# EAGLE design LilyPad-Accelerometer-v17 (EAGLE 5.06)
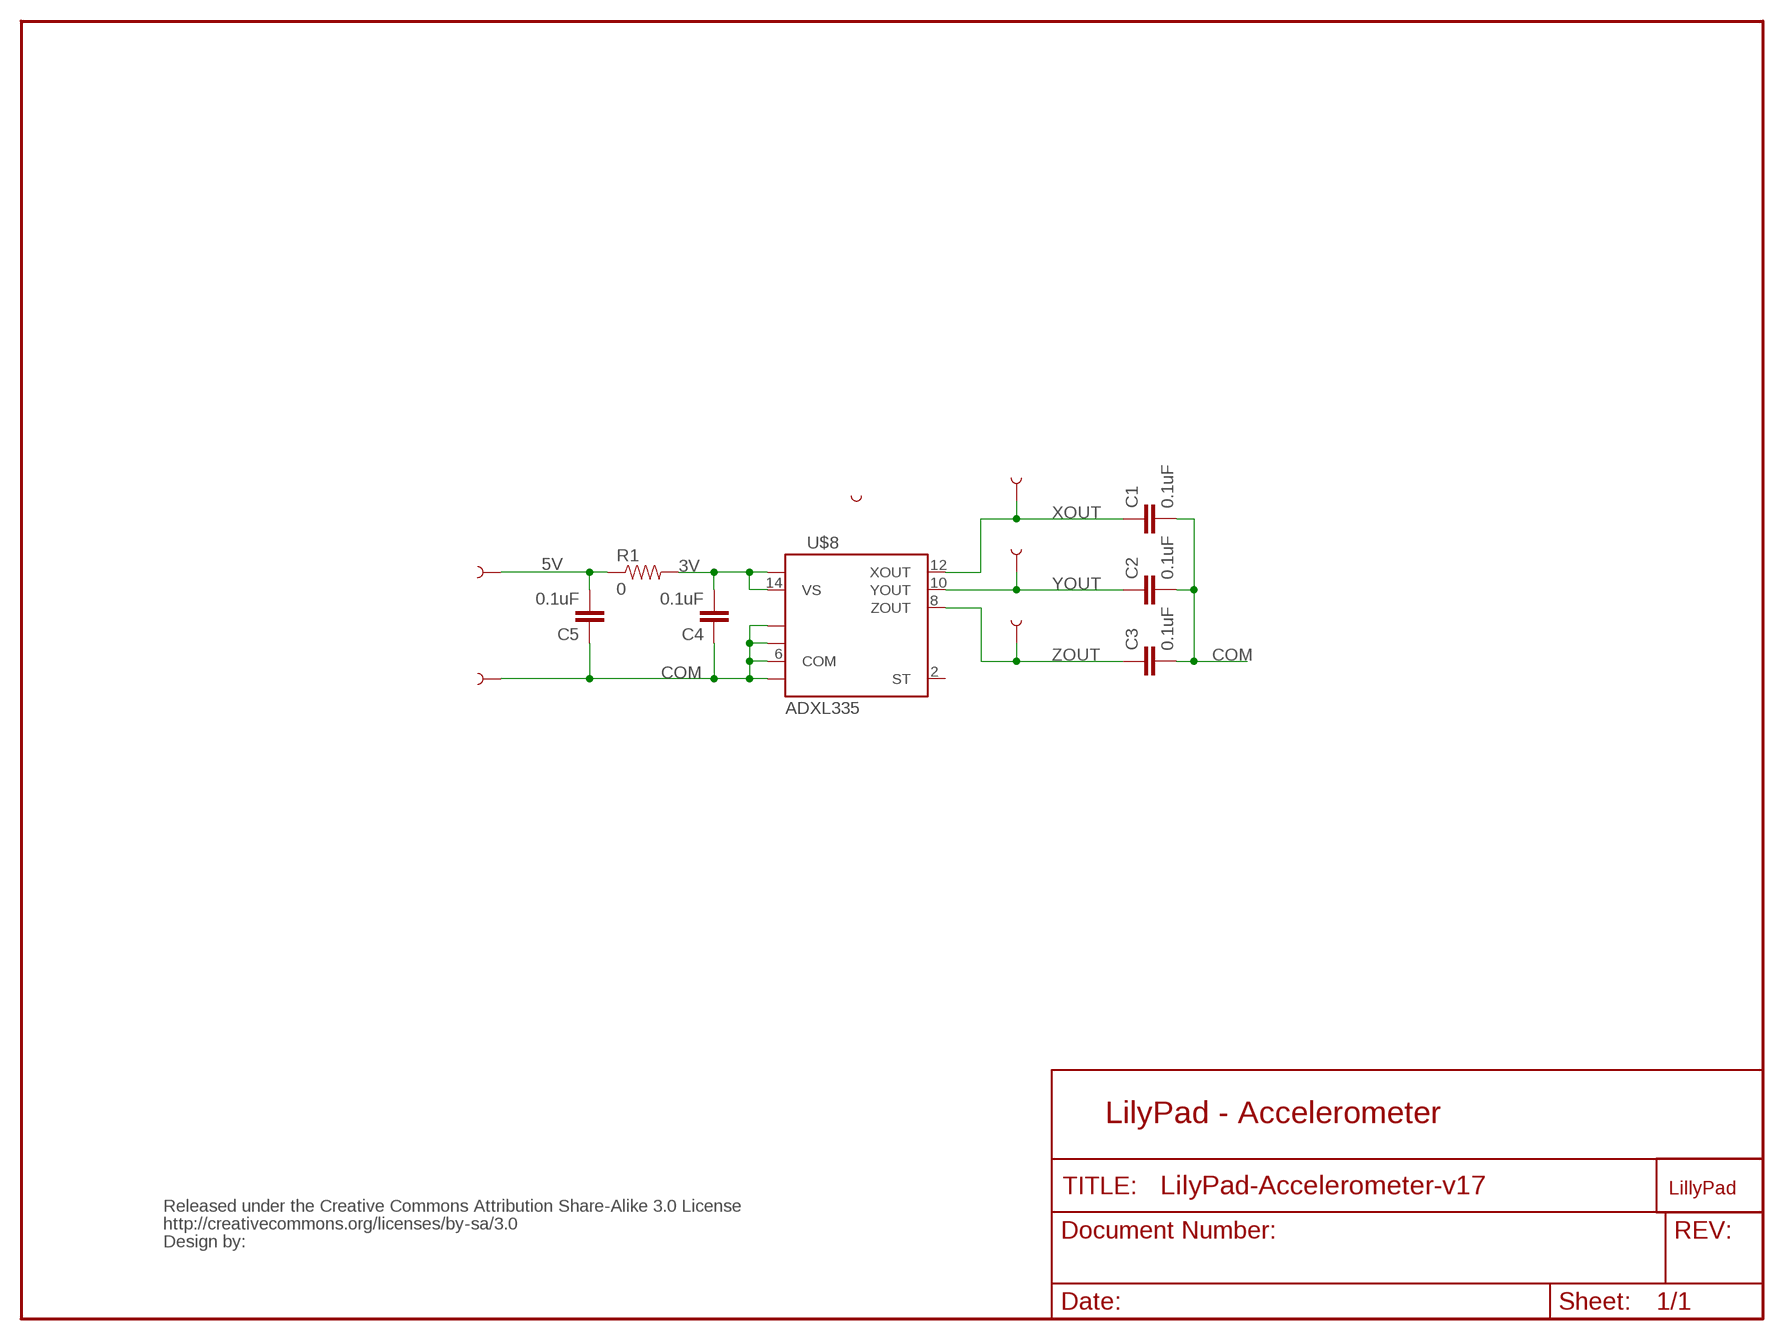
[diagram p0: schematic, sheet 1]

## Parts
C1  0.1uF  CAP0402  [C0402]
C2  0.1uF  CAP0402  [C0402]
C3  0.1uF  CAP0402  [C0402]
C4  0.1uF  CAP0402  [C0402]
C5  0.1uF  CAP0402  [C0402]
R1  0  RESISTOR0402  [C0402]
U$1  SEWTAP3  [SEWTAP-SMALL]
U$2  SEWTAP3  [SEWTAP-SMALL]
U$3  SEWTAP3  [SEWTAP-SMALL]
U$4  LOGO-LP  LOGO-LPLP  [LOGO-LILYPAD]
U$5  SEWTAP3  [SEWTAP-SMALL]
U$6  SEWTAP3  [SEWTAP-SMALL]
U$7  CREATIVE_COMMONS  [CREATIVE_COMMONS]
U$8  ADXL335  [LFCSP-16]
U$13  SEWTAP-NOHOLE  [SEWTAP-NOHOLE]

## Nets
3V: C4.2 R1.2 U$8.14(VS) U$8.15(VS)
5V: C5.2 R1.1 U$6.1
COM: C1.2 C2.2 C3.2 C4.1 C5.1 U$1.1 U$8.3(COM) U$8.5(COM) U$8.6(COM) U$8.7(COM)
XOUT: C1.1 U$2.1 U$8.12(XOUT)
YOUT: C2.1 U$3.1 U$8.10(YOUT)
ZOUT: C3.1 U$5.1 U$8.8(ZOUT)
Unconnected: U$8.2(ST)

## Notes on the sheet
- LilyPad - Accelerometer

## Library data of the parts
C1-C5 = SparkFun:CAP: Capacitor
R1 = SparkFun:RESISTOR: Resistor
U$1-U$3 U$5 U$6 = LilyPad-Wearables:SEWTAP
U$4 = LilyPad-Wearables:LOGO-LP
U$7 = SparkFun:CREATIVE_COMMONS
U$8 = SparkFun:ADXL335
U$13 = LilyPad-Wearables:SEWTAP-NOHOLE

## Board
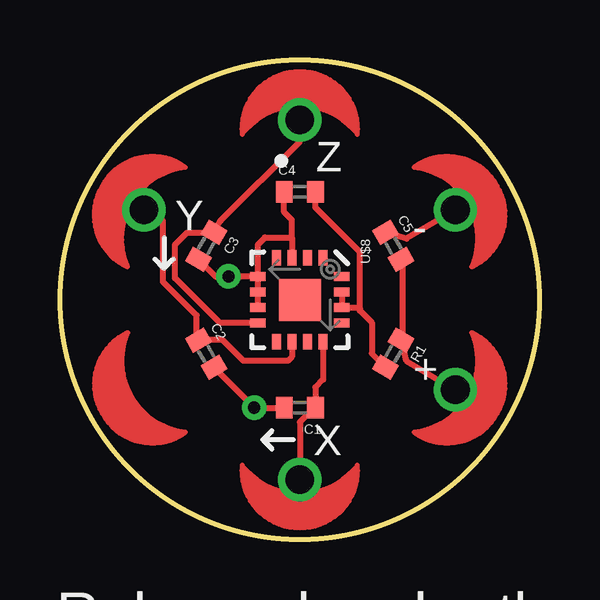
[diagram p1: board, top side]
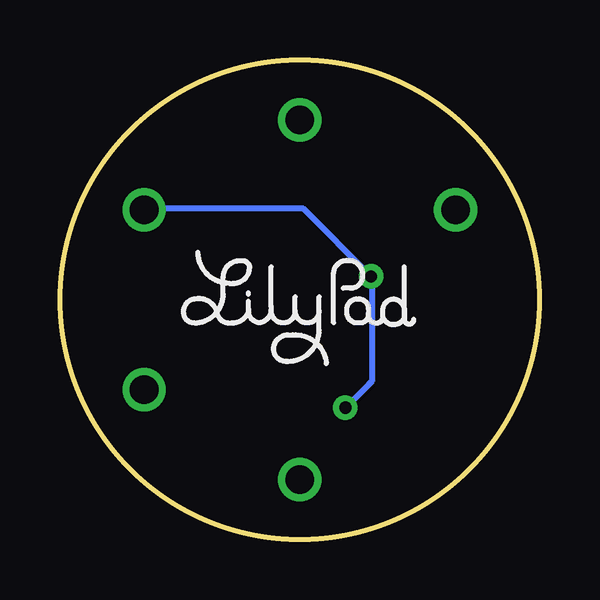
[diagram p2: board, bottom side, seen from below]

Size 20 x 20 mm. Coordinates in mm from the lower left corner, seen from the top.
Outline: circle at 10,10 radius 10
Copper layers (1*16): Top 0.035mm / dielectric 1.5mm / Bottom 0.035mm
Design rules "SparkFun": minimum track width 8mil, minimum drill 20mil, track to track 8mil, track to pad 8mil, pad to pad 8mil, via to via 8mil, smd to smd 8mil, copper to edge 10mil, drill to drill 8mil, minimum pad ring 12mil, minimum via ring 10mil, stop-mask expansion 4mil, vias tented up to drill 20mil, thermal gap 10mil

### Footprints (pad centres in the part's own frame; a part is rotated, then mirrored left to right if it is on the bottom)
C0402 = smd 0.7 x 0.9: 1 -0.65,0; 2 0.65,0
SEWTAP-SMALL = drill 1.2 round: 1 0,0
LFCSP-16 = smd 1.75 x 1.75: 0 0,0 | smd 0.65 x 0.37: 1 -1.75,0.975; 2 -1.75,0.325; 3 -1.75,-0.325; 4 -1.75,-0.975; 9 1.75,-0.975; 10 1.75,-0.325; 11 1.75,0.325; 12 1.75,0.975 | smd 0.37 x 0.65: 5 -0.975,-1.75; 6 -0.325,-1.75; 7 0.325,-1.75; 8 0.975,-1.75; 13 0.975,1.75; 14 0.325,1.75; 15 -0.325,1.75; 16 -0.975,1.75

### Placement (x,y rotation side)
C1  10,5.5 180 top
C2  6.1,7.75 300 top
C3  6.1,12.25 240 top
C4  10,14.5 0 top
C5  13.9,12.25 300 top
R1  13.9,7.75 240 top
U$1  16.49,13.75 210 top
U$2  10,2.5 90 top
U$3  3.5,13.75 330 top
U$4  10,10 0 bottom
U$5  10,17.5 270 top
U$6  16.49,6.25 150 top
U$7  not placed on the board
U$8  10,10 270 top
U$13  3.51,6.25 30 top

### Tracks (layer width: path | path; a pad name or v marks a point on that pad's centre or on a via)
3V
  Top 0.254: R1.2 13,7.76 13,9.05 12.5,9.55 12.5,9.65 | C4.2 10.65,13.85 12.5,12 12.5,9.65 | 12.5,9.65 12.47,9.68 U$8.14 U$8.15
5V
  Top 0.254: U$6.1 14.45,7.45 14.25,8.3 R1.1 14.24,8.3 14.3,8.3 14.3,11.61 C5.2
COM  (via drill 0.51)
  Top 0.254: U$1.1 14.45,12.55 13.55,12.8 C5.1 | 9.68,12.6 9.68,13.32 9.35,13.65 C4.1 | C3.2 5.78,11.68 6.47,10.97 | v7.03,10.97 7,10.95 7,11 | 6.47,10.97 6.97,10.97 7,11 | 9.68,12.6 8.55,12.6 8.25,12.3 U$8.5 | C2.2 8.1,5.51 v8.1,5.5 C1.2 | v7.03,10.97 7.05,11 | 7,11 v7.03,10.97 | U$8.5 6.48,10.97 6.47,10.98 | U$8.7 U$8.6 | U$8.6 U$8.5 | 9.68,12.6 U$8.3 | U$8.6 U$8.5 | 6.47,10.98 6.47,10.97 | 6.47,10.98 6.19,11.27
  Bottom 0.254: 7.1,6.5 v8.1,5.5 | 7.1,6.5 7.03,6.58 | U$1.1 16.5,13.8 9.85,13.8 v7.03,10.97 7,10.95 7,6.6 7.1,6.5
XOUT
  Top 0.254: U$2.1 10,4.9 10.6,5.5 C1.1 10.65,6.35 10.97,6.67 U$8.12
YOUT
  Top 0.254: 5.75,8.3 5.76,8.31 C2.1 | C2.1 6.79,8.31 7.65,7.45 9.5,7.45 9.68,7.62 U$8.10 | U$3.1 4.3,13.3 4.3,10.75 5.7,9.35 5.7,8.3 5.76,8.3 C2.1
ZOUT
  Top 0.254: 6.4,12.8 C3.1 | 6.4,12.8 6.7,13.3 10,16.6 U$5.1 | 6.4,12.8 6.41,12.81 C3.1 | 6.4,12.8 6.41,12.8 C3.1 | 6.4,12.8 5.3,12.8 4.8,12.3 4.8,10.9 6.67,9.03 U$8.8

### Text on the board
tPlace: Z | Y | - | + | X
